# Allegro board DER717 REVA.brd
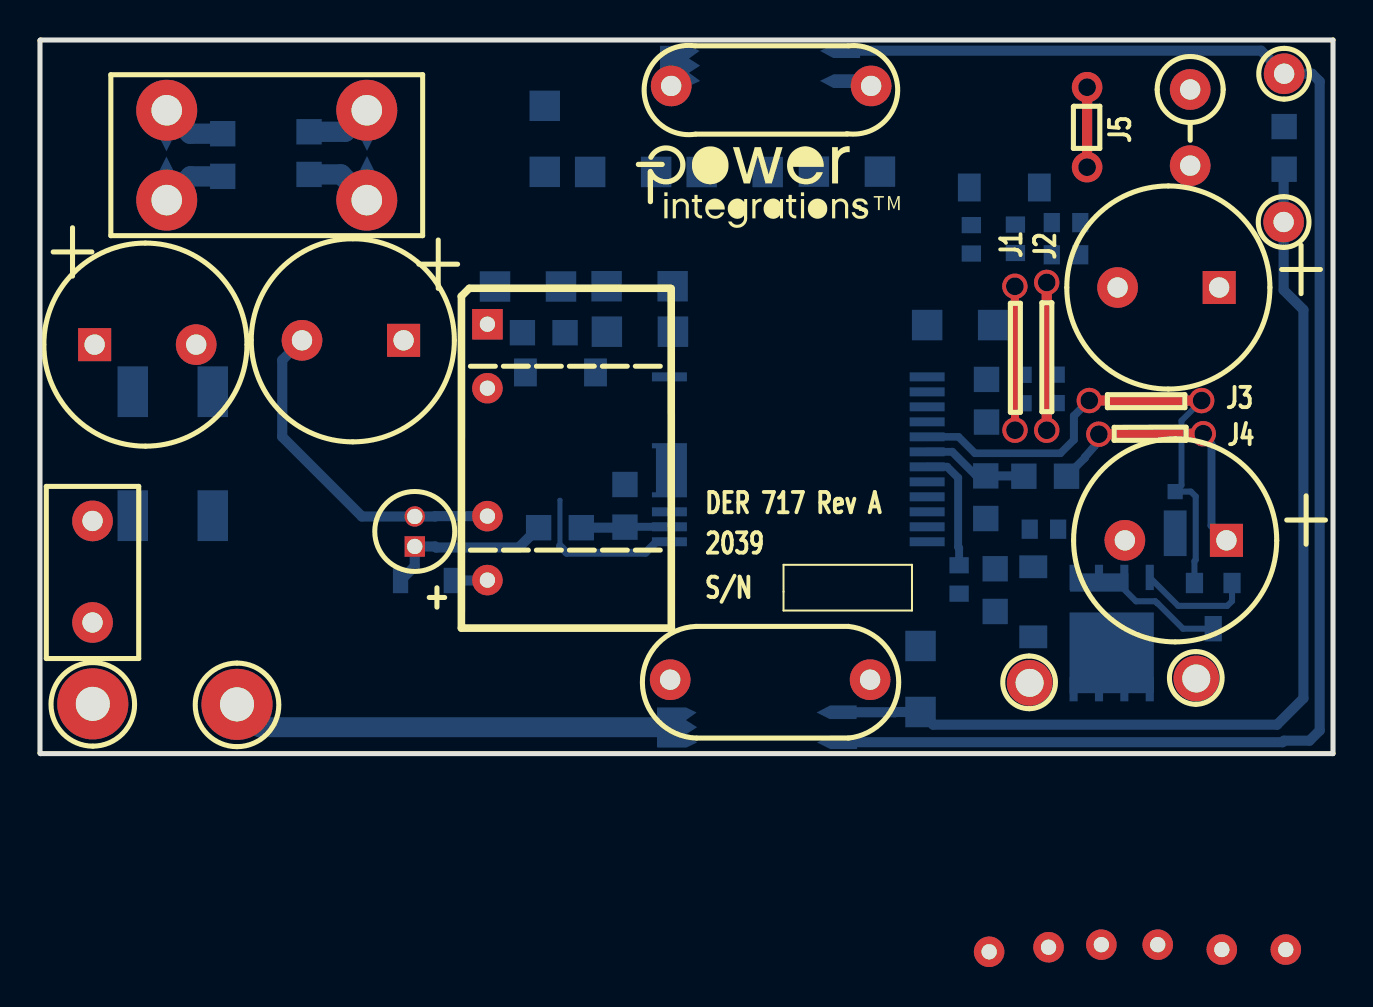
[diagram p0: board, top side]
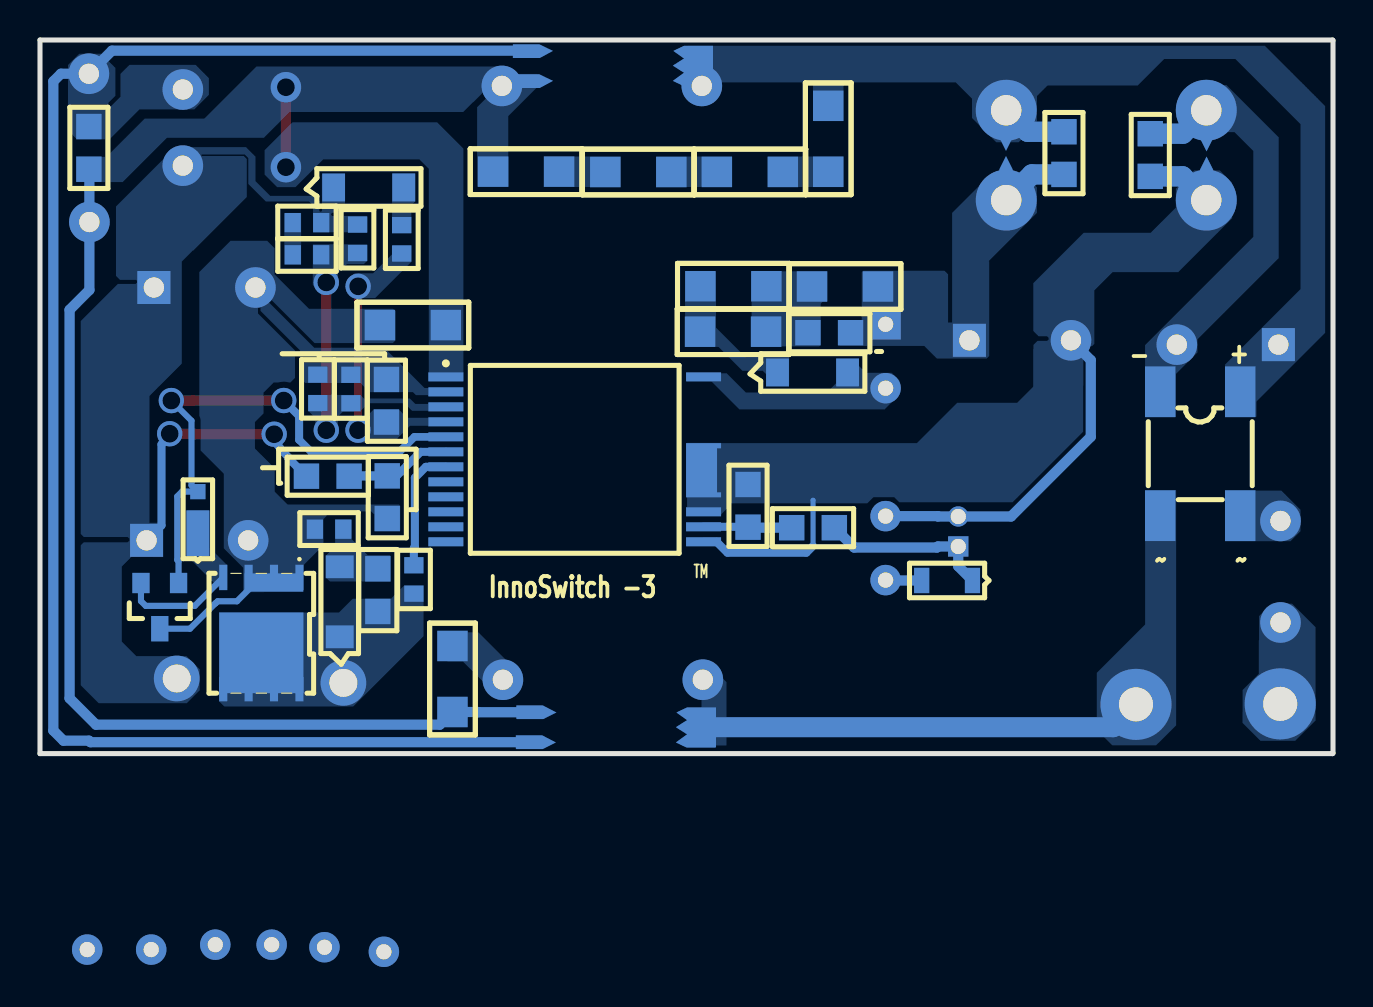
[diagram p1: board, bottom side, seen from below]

Outline 64.68 x 35.7 mm; copper layers: TOP, BOTTOM. Coordinates in mm from the lower left corner of the outline.
Outline path: 0,35.68 0,0.02 0.02,0 64.68,0 64.68,35.7 0.02,35.7 0,35.68

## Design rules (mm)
constraint set DEFAULT: min track width 0.508

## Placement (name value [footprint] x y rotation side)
BR1  FTB10F-15FTR  [PISMD_4SMD]  4.64 18.1 0 bottom
C1  18 uf  [PIPOLCAPCYLD400LS200040]  2.73 20.46 0 top
C2  18 uf  [PIPOLCAPCYLD400LS200040]  18.19 20.68 180 top
C3  1 nF  [PISMC0805]  24.13 21.06 0 bottom
C4  0.47 uF  [PISMC0805]  29.26 11.33 90 bottom
C5  10 uF  [PIPOLCAP4P0X11P0XLS1P5D030]  18.75 10.36 90 top
C6  1 nF  [PISMC0603]  49.5 11.23 0 bottom
C7  470 uF  [PIPOLCAPCYLD400LS200040]  59.34 10.67 180 top
C8  470 uF  [PIPOLCAPCYLD400LS200040]  58.98 23.32 180 top
C9  2.2 uF  [PISMC0805]  47.35 18.72 270 bottom
C10  330 pF  [PISMC0603]  49.12 18.95 270 bottom
C11  2.2 uF  [PISMC0805]  47.31 11.76 90 bottom
C12  47 nF  [PISMC0603]  50.61 26.56 0 bottom
C13  2.2 uF  [PISMC0805]  62.23 31.37 270 bottom
C14  1 nF  [PINPYCAPRAD540X290LS400040]  31.57 33.4 0 top
C15  1 nF  [PINPYCAPRAD540X290LS400040]  31.52 3.7 0 top
D1  S1ML  [PI_SM_SOD-123_12]  27.79 19.07 180 bottom
D2  BAV19WS  [PISMSOD323]  18.03 8.66 0 bottom
D3  PD3S140-7  [PISMD_POWERDI323]  56.78 11.02 270 bottom
D4  S1ML  [PI_SM_SOD-123_12]  49.68 5.84 90 bottom
F1  1 A  [PI_RST_MICROFUSE]  2.63 6.56 90 top
FL1  Hole_50mils  [PI_HOLE_50MIL]  57.84 3.76 0 top
FL2  Hole_50mils  [PI_HOLE_50MIL]  49.5 3.54 0 top
GND  BLK  [PITPKEYSTONE100X100]  62.2 26.59 0 top
L  BLK  [PITPKEYSTONE125X125]  2.64 2.49 0 top
L1  20 mH  [PI_IND_4P_590X295LS394X177D060]  16.32 27.71 0 top
L2  Ferrite Bead (3.5 x 4.45 mm)  [PI12WRESD180LS675D040]  57.53 29.41 90 top
N  WHT  [PITPKEYSTONE125X125]  9.86 2.46 0 top
NOREF  -  []  -228.6 -144.78 0 top
NOREF#2  -  []  0 0.02 90 top
NOREF#3  -  []  29.82 30.86 0 top
NOREF#4  -  []  -150.79 54.23 0 top
NOREF#5  -  []  0.02 35.7 0 top
Q1  TSM160N10LCR  [PISMPQFN5X6B]  51.7 8.81 0 bottom
Q2  AO3415A  [PISMSOT23123_1]  59.62 8.53 0 bottom
R1  4.7 k  [PISMR0805]  13.46 31.11 270 bottom
R2  4.7 k  [PISMR0805]  9.14 31.01 270 bottom
R3  220 k  [PISMR1206]  22.76 23.37 0 bottom
R4  150  [PISMR1206]  28.34 23.38 0 bottom
R5  150  [PISMR1206]  28.36 21.11 0 bottom
R7  3 k  [PISMR0805]  24.94 11.3 0 bottom
R9  47  [PISMR0603]  45.97 8 90 bottom
R10  10  [PISMR0805]  47.78 7.11 90 bottom
R11  100 k  [PISMR0603]  48.79 26.47 270 bottom
R12  10 k  [PISMR0603]  52.03 24.95 180 bottom
R13  11.5 k  [PISMR0603]  50.78 17.53 90 bottom
R14  0.015  [PISMR1206]  47.68 21.44 180 bottom
R15  10 M  [PISMR1206]  25.25 32.41 270 bottom
R16  10 M  [PISMR1206]  27.52 29.1 0 bottom
R17  10 M  [PISMR1206]  33.1 29.09 0 bottom
R18  10 M  [PISMR1206]  38.71 29.11 0 bottom
R19  150  [PISMR1206]  44.04 5.38 270 bottom
R20  330  [PISMR0603]  46.58 25.02 90 bottom
R21  100  [PISMR0805]  49.21 13.88 0 bottom
T1  ATQ17/11.5  [PI_BOBBIN_ATQ17_H_10P]  26.33 14.78 180 top
U1  INN3164C-H101  [PI_IC_INSOP_24D]  44.37 18.85 180 bottom
VO  RED  [PITPKEYSTONE100X100]  62.23 34.01 0 top
VR2  MMSZ5242B-7-F  [PI_SM_SOD-123_12]  49.99 28.32 180 bottom

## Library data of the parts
BR1 = DIODE BRIDGE_+-~~
C1 C2 C7 C8 = CAP POL: alternate symbols: (pipolcapclyd395x630ls200030h)
C3 C4 C6 C9 C11-C13 = CAP NP
C5 = CAP POL
C10 = CAP NP: alternate symbols: (pismc0603_1)
C14 C15 = CAP NP: alternate symbols: (pinpycaprad540x290ls400040h,pinpycaprad500x220ls400040)
D1-D4 = DIODE
F1 = FUSE: alternate symbols: (pirstmicrofusehoz)
FL1 FL2 = FlyingLead
GND L N VO = TESTPOINT
L1 = INDUCTOR_4P_revD
L2 = INDUCTOR: alternate symbols: (pi12wvresd180ls150d040,pi12wvresd180ls200d040,pi12wvresd180ls250d040)
Q1 = FET_N_SGD_123_4_5678
Q2 = FET_P_GSD
R1-R3 R7 R10-R18 R20 R21 = R
R4 R5 R19 = R: alternate symbols: (pismr1206_1)
R9 = R: alternate symbols: (pismr0603_1)
T1 = BATQ17_10P/GENERIC
U1 = Inno3CE_P15
VR2 = DIODE_ZENER

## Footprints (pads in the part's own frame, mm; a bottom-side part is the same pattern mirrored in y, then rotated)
PI12WRESD180LS675D040
  round 2.032 hole 1.016: 1(0,0) 2(3.81,0)
PI_BOBBIN_ATQ17_H_10P
  rect 1.524x1.524 hole 0.762: 1(3.949,-6.701)
  round 1.524 hole 0.762: 2(3.949,-3.501) 3(-21.146,24.693) 4(3.949,2.899) 5(3.949,6.099) 6(-35.985,24.582) 7(-32.785,24.582) 8(-29.579,24.337) 9(-26.76,24.338) 10(-24.118,24.465)
PI_HOLE_50MIL
  round 2.286 hole 1.4: 1(0,0)
PI_IC_INSOP_24D
  rect 1.75x0.45 smd: 1(0,0) 2(0,-0.75) 3(0,-1.5) 4(0,-2.25) 5(0,-3) 6(0,-3.75) 7(0,-4.5) 8(0,-5.25) 9(0,-6) 10(0,-6.75) 11(0,-7.5) 12(0,-8.25) 13(12.89,-8.25) 14(12.89,-7.5) 15(12.89,-6.75) 24(12.89,0)
  custom 0.438x0.438 smd: 16(12.89,-4.67)
PI_IND_4P_590X295LS394X177D060
  round 3.048 hole 1.524: 1(0.025,-0.025) 2(0.025,4.47) 3(-9.982,4.47) 4(-9.982,-0.025)
PI_RST_MICROFUSE
  round 2.032 hole 1.016: 1(0,0) 2(5.08,0)
PI_SM_SOD-123_12
  rect 1.143x1.397 smd: 1(0,0) 2(3.505,0)
PINPYCAPRAD540X290LS400040
  round 2.032 hole 1.016: 1(0,0) 2(10,0)
PIPOLCAP4P0X11P0XLS1P5D030
  rect 1.016x1.016 hole 0.762: 1(0,0)
  round 1.016 hole 0.762: 2(1.5,0)
PIPOLCAPCYLD400LS200040
  rect 1.651x1.651 hole 1.016: 1(0,0)
  round 2.032 hole 1.016: 2(5.08,0)
PISMC0603
  rect 0.813x0.965 smd: 1(0,0) 2(1.422,0)
PISMC0805
  rect 1.27x1.27 smd: 1(0,0) 2(2.134,0)
PISMD_4SMD
  rect 1.524x2.54 smd: 1(0,0) 2(4,0) 3(4,6.2) 4(0,6.2)
PISMD_POWERDI323
  rect 2.286x1.143 smd: 1(0,0)
  rect 0.762x0.762 smd: 2(-2.083,0)
PISMPQFN5X6B
  rect 0.406x1.27 smd: 1(0,0) 2(1.27,0) 3(2.54,0) 4(3.81,0)
  rect 0.406x1.219 smd: 5(3.81,5.588) 6(2.54,5.588) 7(1.27,5.588) 8(0,5.588)
PISMR0603
  rect 0.813x0.965 smd: 1(0,0) 2(1.422,0)
PISMR0805
  rect 1.27x1.27 smd: 1(0,0) 2(2.134,0)
PISMR1206
  rect 1.524x1.524 smd: 1(0,0) 2(3.302,0)
PISMSOD323
  rect 0.762x1.27 smd: 1(0,0) 2(2.54,0)
PISMSOT23123_1
  rect 0.864x1.016 smd: 1(-1.88,0) 2(0,0)
  rect 0.864x1.27 smd: 3(-0.94,2.286)
PITPKEYSTONE100X100
  round 2.032 hole 1.016: 1(0,0)
PITPKEYSTONE125X125
  round 3.556 hole 1.702: 1(0,0)

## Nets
NC8: U1.8
NC9: U1.9
NC10: U1.10
NC11: U1.11
NC12: U1.12
SPARK GAP A 6 MM: BR1.1 C1.1 C14.1 L1.2 R1.1 R15.1
SPARK GAP B 6 MM: BR1.3 C15.1 N.1
SPARK GAP GND: C13.2 C14.2 GND.1 R14.2 R18.2 R19.2 U1.1
SPARK GAP VO: C13.1 L2.2 VO.1
N05007: BR1.2 C1.2 L1.3 R2.1
N05208: C2.1 C3.1 L1.1 R1.2 R3.1 T1.1
N05228: C2.2 C4.2 C5.2 L1.4 R2.2 T1.4 U1.13(VPIN) U1.15 U1.16
N06587: C3.2 R3.2 R4.1 R5.1
N06642: D1.1 R4.2 R5.2
N06679: D1.2 T1.2 U1.24
N06800: C4.1 R7.2 U1.14
N06937: D2.2 T1.5
N06978: C5.1 D2.1 R7.1
N12310296: R9.2 U1.7
N12310343: D3.2 Q2.1 U1.5
N12310347: D3.1 Q1.4 Q2.2(S)
N12310367: D4.1 FL2.1 Q1.5 Q1.6 Q1.7 Q1.8 R9.1 R10.1
N12310400: C6.2 C7.2 C8.2 C9.1 C10.1 C11.1 Q1.1 Q1.2 Q1.3(S3) Q2.3 R13.2 R14.1 U1.2
N12325405: C6.1 D4.2 R10.2
N12325650: C7.1 C8.1 C12.1 FL1.1 L2.1 R11.1 R21.2 VR2.1
N12325783: C9.2 R20.1 U1.4
N12326606: C10.2 R11.2 R12.2 R13.1 U1.3
N12326726: C11.2 R21.1 U1.6
N12328885: R15.2 R16.1
N12328893: R16.2 R17.1
N12328897: R17.2 R18.1
N12330008: R20.2 VR2.2
N12331495: BR1.4 F1.2
N12339011: C15.2 R19.1
N12348785: F1.1 L.1
N12358873: C12.2 R12.1

Pads without a net: T1 3 6 7 8 9 10

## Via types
v1: diameter 1.524, hole 0.889, TOP to BOTTOM, 2 vias
v2: diameter 1.27, hole 0.889, TOP to BOTTOM, 8 vias

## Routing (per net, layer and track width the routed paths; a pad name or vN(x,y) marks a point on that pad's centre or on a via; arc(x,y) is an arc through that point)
SPARK GAP A 6 MM: length 3.3
  BOTTOM w1.016: R1.1 15.27,31.11 L1.2
SPARK GAP B 6 MM: length 22
  BOTTOM w0.254: 31.57,1.23 31.56,1.22
  BOTTOM w1: 31.34,1.32 11,1.32 N.1
SPARK GAP GND: length 55.1
  TOP w0.508: v1(52.37,29.34) v1(52.37,33.34)
  BOTTOM w0.508: C13.2 62.2,29.21 GND.1 62.2,23.19 63.19,22.2 63.19,2.77 61.87,1.45 44.68,1.45 R19.2 42.77,2.08 42.76,2.07 39.84,2.07
SPARK GAP VO: length 81.7
  BOTTOM w0.508: 39.84,35.16 61.08,35.16 VO.1 63.63,34.01 64.01,33.63 64.01,1.15 63.5,0.65 62.22,0.65 62.15,0.57 39.84,0.57
N05007: length 3.3
  BOTTOM w1.016: L1.3 6.34,32.18 7.51,31.01 R2.1
N05208: length 3.4
  BOTTOM w1.016: L1.1 15.06,28.97 R1.2
N05228: length 28.6
  BOTTOM w0.25: 26.01,10.39 26.01,10.39 26.01,12.67 26.01,12.67
  BOTTOM w0.4: 26.01,10.39 26.34,10.05 30.29,10.05 30.83,10.6 U1.13
  BOTTOM w0.508: T1.4 19.78,11.88 19.76,11.86 C5.2 16.1,11.86 12.12,15.85 12.12,19.68 C2.2
  BOTTOM w1.016: L1.4 6.34,27.69 7.53,28.88 R2.2
N06800: length 4.4
  BOTTOM w0.4: U1.14 29.28,11.35
  BOTTOM w0.45: 29.28,11.35 C4.1
  BOTTOM w0.508: R7.2 29.24,11.3 C4.1
N06937: length 1.8
  BOTTOM w0.508: T1.5 22.36,8.66 D2.2
N06978: length 8.6
  BOTTOM w0.508: R7.1 23.95,10.31 19.82,10.31 19.76,10.36 C5.1 18.75,9.37 D2.1
N12310296: length 6.2
  BOTTOM w0.4: R9.2 45.97,10.28 45.92,10.33 45.92,13.8 45.37,14.35 U1.7
N12310343: length 26.5
  TOP w0.508: v2(58.1,17.66) 57.04,17.66 57.03,17.66 v2(52.48,17.66)
  BOTTOM w0.3: v2(58.1,17.66) 57.1,16.65 57.1,13.42 D3.2
  BOTTOM w0.305: D3.2 57.57,13.11 57.81,12.87 57.81,9.69 57.74,9.63 Q2.1
  BOTTOM w0.381: U1.5 45.94,15.85 46.77,15.02 51.04,15.02 51.71,15.7
  BOTTOM w0.4: 51.71,15.7 51.71,16.89 v2(52.48,17.66)
N12310347: length 5.7
  BOTTOM w0.305: Q1.4 56.93,7.39 59.38,7.39 59.62,7.63 Q2.2
N12310400: length 5.3
  BOTTOM w0.305: 54.24,8.2 54.82,7.62 55.79,7.62 55.89,7.52 55.9,7.52 57.17,6.25 Q2.3
N12325650: length 13.8
  TOP w0.508: v2(52.96,15.98) 56.92,15.98 56.95,16 v2(58.19,16)
  BOTTOM w0.4: v2(52.96,15.98) 52.76,15.78 52.76,15.4 52.27,14.83 52.27,14.8 R21.2 ; v2(58.19,16) 58.19,15.88 58.6,15.47 58.6,11.41 C7.1
N12325783: length 7.2
  TOP w0.4: v2(48.77,16.18) 48.77,22.23 48.76,22.24 v2(48.76,23.38)
N12326606: length 7.4
  TOP w0.508: v2(50.35,16.18) v2(50.35,23.57)
N12326726: length 5.3
  BOTTOM w0.4: U1.6 45.63,15.1 46.83,13.89 C11.2
  BOTTOM w0.457: C11.2 49.2,13.89 R21.1

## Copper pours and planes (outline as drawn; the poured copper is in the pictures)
SPARK GAP A 6 MM on BOTTOM (solid shape): 16.69,30.82 16.36,30.15 16.02,30.82 16.02,32.15 16.69,32.15
SPARK GAP A 6 MM on BOTTOM (solid shape): 32.99,35.15 32.46,34.77 33.02,34.42 32.46,34.06 33.02,33.66 32.49,33.4 31.04,33.4 31.01,33.43 31.01,35.41 32.46,35.41
SPARK GAP A 6 MM on BOTTOM: 0.39,32.4 3.4,35.41 32.26,35.41 32.26,33.22 32,32.97 31.29,32.97 30.68,33.58 26.01,33.58 26.01,31.67 25.98,31.65 24.49,31.65 24.49,33.55 24.46,33.58 18.87,33.58 18.06,32.77 18.06,31.8 16.84,30.58 15.72,30.58 15.35,30.96 14.81,31.5 14.81,32.89 14.28,33.42 9.76,33.42 8.44,34.75 4.89,34.75 4.29,34.16 1.63,31.49 1.63,23.23 3.53,21.33 5.4,19.46 5.4,16.85 3.85,16.85 3.83,16.87 3.83,17.62 1.83,19.61 0.39,21.05
SPARK GAP B 6 MM on BOTTOM (solid shape): 32.84,2.06 32.31,1.68 32.87,1.32 32.31,0.97 32.87,0.56 32.33,0.3 30.89,0.3 30.86,0.33 30.86,2.31 32.31,2.31
SPARK GAP B 6 MM on BOTTOM: 30.34,3.58 30.34,0.41 30.34,0.41 31.59,0.41 31.59,2.44 31.58,2.44 31.58,2.67 32.29,3.38 32.29,4.01 31.84,4.46 31.22,4.46
SPARK GAP B 6 MM on BOTTOM: 7.87,13.18 9.4,13.18 9.4,6.46 11.82,4.04 11.82,1.19 11.04,0.42 8.85,0.42 8.69,0.57 8.69,0.57 7.85,1.41 7.85,13.15
SPARK GAP GND on BOTTOM (solid shape): 41.02,33.3 39.67,33.3 39.01,33.66 39.7,33.99 41.02,33.99
SPARK GAP GND on BOTTOM (solid shape): 40.85,1.75 40.82,1.73 39.5,1.73 38.84,2.06 39.53,2.41 40.85,2.41
SPARK GAP GND on BOTTOM: 43.5,18.61 45.21,18.61 45.23,18.63 45.23,29.26 45.69,29.73 50.5,29.73 51.89,28.34 52.81,28.34 53.44,28.97 53.44,30.19 52.05,31.58 44.81,31.58 43.5,30.27 43.5,18.61
SPARK GAP GND on BOTTOM: 41.25,31.89 41.25,28.35 42.77,28.35 42.81,28.39 42.81,32.34 42.31,32.84 42.31,33 42.41,33.09 42.5,33.09 43,32.59 43.01,32.59 43.5,32.1 52.18,32.1 53.47,30.81 58.32,30.81 60.54,28.59 62.86,28.59 62.86,28.59 62.86,29.86 62.86,29.87 61.66,29.87 61.64,29.85 61.35,29.85 59.44,31.77 56.45,31.77 53.85,34.37 41.45,34.37 41.07,34 40.86,34 40.86,34 39.8,34 39.8,34 39.8,33.34
SPARK GAP VO on BOTTOM (solid shape): 41.02,34.8 39.67,34.8 39.01,35.15 39.7,35.48 41.02,35.48
SPARK GAP VO on BOTTOM (solid shape): 40.87,0.25 40.85,0.23 39.53,0.23 38.87,0.56 39.55,0.91 40.87,0.91
SPARK GAP VO on BOTTOM: 56.23,33.79 56.23,32.95 56.95,32.23 59.7,32.23 61.19,30.73 62.83,30.73 63.28,31.18 63.28,34.45 62.71,35.01 61.61,35.01 60.9,34.3 60.9,32.91 61.26,32.55 61.26,32.42 61.22,32.38 61.13,32.38 60.65,32.86 60.65,34 60.2,34.45 56.89,34.45
N05007 on BOTTOM (solid shape): 6.66,30.79 6.33,30.13 5.99,30.79 5.99,32.12 6.66,32.12
N05007 on BOTTOM: 3.99,25.85 3.99,30.15 4.93,31.09 6.93,31.09 7.44,31.6 7.44,32.79 6.79,33.44 5.33,33.44 2.72,30.83 2.72,24.78 6.78,20.72 6.78,20.07 7.87,18.98 7.87,16.85 9.4,16.85 9.4,20.44
N05208 on BOTTOM (solid shape): 16.69,29.23 16.69,27.9 16.02,27.9 16.02,29.23 16.36,29.9
N05208 on BOTTOM: 15.47,28.98 17.12,28.98 19.05,27.05 19.05,21.56 19.25,21.56 19.25,23.98 19.43,24.16 23.5,24.16 23.57,24.08 23.57,21.69 23.67,21.59 24.71,21.59 24.71,20.45 24.66,20.4 20.45,20.4 19.81,19.76 17.32,19.76 17.2,19.89 17.2,24.61 17.22,24.64 14.81,27.05 14.81,28.32
N05228 on BOTTOM (solid shape): 6.66,29.2 6.66,27.87 5.99,27.87 5.99,29.2 6.33,29.87
N05228 on BOTTOM: 5.67,29.18 6.94,29.18 7.86,28.26 7.86,27.31 9.12,26.05 12.47,26.05 14.99,23.54 14.99,21.14 14.76,20.91 14.76,20.9 14.73,20.88 14.3,20.88 14.22,20.8 14.22,20.72 14.29,20.65 14.78,20.65 14.99,20.44 14.99,18.14 14.71,18.41 12.5,18.41 12.5,20.39 12.49,20.39 12.05,20.39 11.94,20.5 11.94,23.17 11.03,24.08 7.74,24.08 5.05,26.78 5.05,28.56
N05228 on BOTTOM: 32.31,15.57 32.28,15.54 30.61,15.54 30.59,15.53 20.82,15.53 18.8,17.55 15.8,17.55 14.99,18.36 14.99,20.22 14.88,20.32 13.13,20.32 12.5,19.68 12.5,16.1 16.03,12.57 21.69,12.57 21.95,12.83 22.99,12.83 23.29,12.52 30.05,12.52 30.66,11.91 32.21,11.91 32.31,12.01
N06587 on BOTTOM: 25.3,24.13 29.08,24.13 29.08,20.37 25.7,20.37 25.63,20.45 25.63,22.5 25.5,22.63 25.3,22.63
N06642 on BOTTOM: 30.86,24.1 30.86,21.31 29.39,19.84 27.2,19.84 27.2,18.44 27.25,18.39 28.27,18.39 28.35,18.47 28.35,18.97 28.52,19.15 29.54,19.15 30.73,20.35 32.41,20.35 32.41,24.1
N06679 on BOTTOM: 22.07,19.05 21.69,18.67 21.69,17.96 22.44,17.21 22.45,17.22 29.69,17.22 31.11,18.64 32.26,18.64 32.28,18.67 32.28,18.97 32.23,19.02 30.33,19.02 29.36,18.06 26.8,18.06 26.79,18.07 25.34,18.07 25.32,18.08 25.3,18.08 24.84,18.54 24.84,19.74 23.72,19.74 23.72,19.41 23.37,19.05
N12310347 on BOTTOM: 56.2,12.17 57.34,12.17 57.34,9.91 55.74,8.31 55.31,8.31 55.31,9.42 56.2,10.31
N12310367 on BOTTOM (solid shape): 55.71,3.02 51.5,3.02 51.5,7.06 55.71,7.06
N12310367 on BOTTOM: 46.45,8.41 47.12,7.75 49.03,7.75 49.72,7.06 55.71,7.06 55.71,7.06 55.71,2.61 55.46,2.36 49,2.36 45.49,5.87 45.49,8.41 45.49,8.41
N12310400 on BOTTOM (solid shape): 54.44,8.1 51.52,8.1 51.52,9.02 54.44,9.02
N12310400 on BOTTOM: 53.44,8.1 51.47,8.1 51.47,9.45 50.5,10.42 50.5,11.73 50.11,12.12 48.11,12.12 47.95,11.96 47.95,11.17 47.91,11.14 46.67,11.14 46.66,11.16 46.66,12.4 46.72,12.46 51.46,12.46 51.46,12.46 52.29,12.46 52.93,13.11 52.93,14.27 53.92,15.27 53.92,16.59 53.49,17.02 53.49,18.06 52.98,18.57 52.15,18.57 51.92,18.8 51.92,20.17 53.77,22.02 53.77,22.33 53.64,22.33 53.64,22.15 51.66,20.17 51.66,18.8 51.41,18.54 48.88,18.54 48.65,18.54 48.19,18.08 46.02,18.08 45.87,17.93 43.79,17.93 43.79,18.29 45.44,18.29 46.74,19.58 46.99,19.84 47.29,20.14 47.45,20.3 50.96,20.3 53.21,22.56 53.21,22.58 53.11,22.68 53.09,22.68 50.94,20.54 47.03,20.54 46.89,20.68 46.89,22.13 47.01,22.25 51.22,22.25 52.94,23.97 52.94,25.28 53.31,25.65 55.14,25.65 56.71,24.09 56.71,15.23 55.48,14 55.48,10.27 54.51,9.3 54.51,8.08 53.47,8.08
N12325405 on BOTTOM: 50.38,9.91 50.38,8.81 50.17,8.61 47.13,8.61 47.13,9.88 47.18,9.93 48.29,9.93 49.1,10.74 49.1,11.71 49.91,11.71 49.91,10.37
N12325650 on BOTTOM: 48.31,26.08 51.02,26.08 51.02,26.09 51.02,27.42 51.22,27.62 53.38,27.62 54.25,28.5 54.25,29.79 54.43,29.97 56.59,29.97 56.59,29.9 54.48,29.9 54.33,29.74 54.33,27.84 57.03,25.14 57.07,25.18 57.07,25.13 57.58,24.61 57.58,19.51 59.2,17.89 59.2,11.55 58.52,11.55 58.52,9.84 58.51,9.83 59.02,9.83 59.03,9.84 60.1,9.84 60.58,9.36 60.58,5.6 59.86,4.88 57.35,4.88 56.69,4.22 56.69,3.17 57.33,2.52 61.74,2.52 62.68,3.47 62.68,10.37 62.49,10.57 60.29,10.57 60.21,10.66 60.21,10.75 60.29,10.84 62.48,10.84 62.67,11.03 62.67,21.6 60.78,23.5 59.89,23.5 59.82,23.57 59.82,23.65 59.87,23.7 60.67,23.7 60.87,23.9 60.87,27.37 57.9,30.34 54.37,30.34 53.89,29.86 53.89,28.64 53.16,27.9 50.97,27.9 50.7,27.64 50.7,27.15 50.67,27.11 50.61,27.11 50.57,27.15 50.57,27.91 50.58,27.91 50.58,28.92 50.48,29.02 49.42,29.02 49.42,27.12 49.48,27.05 50.06,27.05 50.11,27 50.11,26.95 50.07,26.9 48.31,26.9
N12325783 on BOTTOM: 46.09,25.42 46.09,24.61 47.91,22.79 49.01,22.79 49.33,23.11 49.33,23.64 48.94,24.03 48.01,24.03 47.07,24.97 47.07,25.42
N12325783 on BOTTOM: 43.89,16.79 43.89,16.41 43.9,16.4 46.17,16.4 47.01,15.56 48.92,15.56 49.27,15.9 49.27,16.47 48.94,16.8 48.4,16.8 47.99,17.21 46.72,17.21 46.31,16.8 43.9,16.8
N12326606 on BOTTOM: 43.85,17.49 43.85,17.16 43.86,17.15 46.07,17.15 46.44,17.53 48.25,17.53 48.65,17.12 49.51,17.12 49.77,16.86 49.77,15.99 50.08,15.69 50.68,15.69 50.9,15.91 50.9,16.79 51.05,16.94 51.23,17.12 51.23,17.95 51.23,17.94 48.65,17.94 48.47,17.76 47.58,17.76 47.58,17.76 46.17,17.76 45.9,17.49
N12326606 on BOTTOM: 48.31,25.48 48.31,24.65 48.31,24.65 48.47,24.49 49.32,24.49 49.77,24.04 49.77,23.39 50.14,23.02 50.61,23.02 51.03,23.44 51.03,25.45 51,25.48
N12328885 on BOTTOM: 24.49,29.87 24.49,28.35 28.27,28.35 28.27,29.87
N12328893 on BOTTOM: 30.07,29.87 30.07,28.35 33.86,28.35 33.86,29.87
N12328897 on BOTTOM: 35.64,29.87 35.64,28.35 39.47,28.35 39.47,29.87
N12330008 on BOTTOM: 46.1,26.03 47.07,26.03 47.07,27.57 47.07,29.02 47.06,29.02 45.9,29.02 45.9,27.62 46.1,27.42 46.1,27.42
N12331495 on BOTTOM: 2.13,10.63 1.63,11.13 1.63,12.2 2.58,13.16 5.38,13.16 5.4,13.14 5.4,10.63
N12339011 on BOTTOM: 40.82,4.14 40.82,3.36 41.23,2.95 41.86,2.95 43.52,4.61 44.28,4.61 44.53,4.85 44.53,5.92 44.37,6.07 42.75,6.07
N12348785 on BOTTOM: 3.71,5.66 3.7,5.68 3.7,6.87 3.07,7.5 2.05,7.5 0.87,6.32 0.87,1.66 1.89,0.64 3.63,0.64 4.53,1.54 4.53,2.09 4.52,2.1 4.52,3.18 3.71,3.99 3.71,5.46 3.71,5.46
N12358873 on BOTTOM: 51.61,27.03 51.61,24.46 52.45,24.46 52.45,27.04 51.62,27.04

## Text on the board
Ref Des/Silkscreen Bottom: TM | InnoSwitch -3
Ref Des/Silkscreen Top: S/N | DER 717 Rev A | 2039 | J3 | J4 | J1 | J2 | J5
User.6: 14.  FAB HOUSE LOGO,DATE CODE TO BE IN SILK SCREEN ONLY.DO NOT USE COPPER. | 13.  MATERIAL FR4 COPPER 2oz THICKNESS 0.062"
